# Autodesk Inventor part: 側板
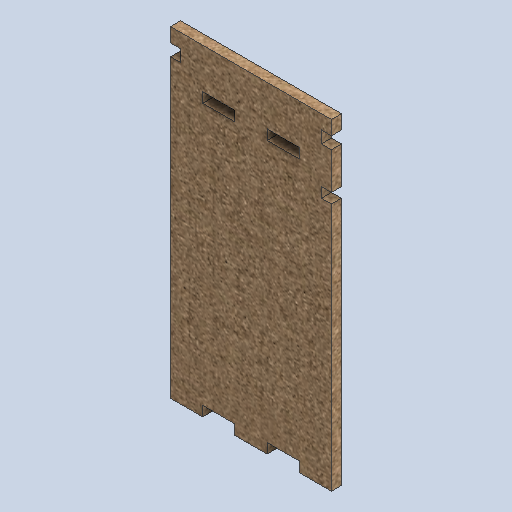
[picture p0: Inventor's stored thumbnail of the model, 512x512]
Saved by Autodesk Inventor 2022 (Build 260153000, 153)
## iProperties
Created: 2024-11
Part Number: 側板
Material: MDF 中密度繊維ボード
Document SubType Name: Modeling
Designer: shimizu
Density: 0.8 g/cm^3
Appearance: ダンボール - 段ボール紙
Author: shimizu
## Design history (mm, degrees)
sketch "スケッチ1"
  geometry: L1 (-20.243, 58.107)-(19.757, 58.107); L2 (-4.243, -21.893)-(-4.243, -19.393); L3 (-4.243, -19.393)-(-12.243, -19.393); L4 (-12.243, -19.393)-(-12.243, -21.893); L5 (11.757, -21.893)-(11.757, -19.393); L6 (11.757, -19.393)-(3.757, -19.393); L7 (3.757, -19.393)-(3.757, -21.893); L8 (-12.243, 48.107)-(-4.243, 48.107); L9 (-4.243, 48.107)-(-4.243, 45.607); L10 (-4.243, 45.607)-(-12.243, 45.607); L11 (-12.243, 45.607)-(-12.243, 48.107); L12 (3.757, 48.107)-(11.757, 48.107); L13 (11.757, 48.107)-(11.757, 45.607); L14 (11.757, 45.607)-(3.757, 45.607); L15 (3.757, 45.607)-(3.757, 48.107); L16 (-12.243, -21.893)-(-20.243, -21.893); L17 (19.757, -21.893)-(11.757, -21.893); L18 (3.757, -21.893)-(-4.243, -21.893); L19 (-20.243, 54.607)-(-17.743, 54.607); L20 (-17.743, 54.607)-(-17.743, 51.607); L21 (-17.743, 51.607)-(-20.243, 51.607); L22 (19.757, 54.607)-(17.257, 54.607); L23 (17.257, 54.607)-(17.257, 51.607); L24 (17.257, 51.607)-(19.757, 51.607); L25 (-20.243, -21.893)-(-20.243, 51.607); L26 (-20.243, 54.607)-(-20.243, 58.107); L27 (19.757, 58.107)-(19.757, 54.607); L28 (19.757, 51.607)-(19.757, -21.893); L29 (19.757, 42.427)-(17.257, 42.427); L30 (17.257, 42.427)-(17.257, 39.917); L31 (17.257, 39.917)-(19.757, 39.917); L32 (19.757, 39.917)-(19.757, 42.427); L33 (-20.243, -13.712)-(-17.743, -13.712); L34 (-17.743, -13.712)-(-17.743, -16.212); L35 (-17.743, -16.212)-(-20.243, -16.212); L36 (-20.243, -16.212)-(-20.243, -13.712); 3 further points
  constraints: 72 end point, 19 parallel, 8 perpendicular, 7 horizontal, 2 point on line
  dimensions: "d27" = 80 distance between parallel lines of L17 L1; "d28" = 40 distance between parallel lines of L25 L28; "d29" = 3.18 distance between parallel lines of L29 L14; "d30" = 2.5 distance of L30.end L31.end; "d31" = 2.5 distance between parallel lines of L16 L3; "d32" = 3.181 distance between parallel lines of L3 L35; "d33" = 2.5 distance of L33.end L34.end; "d34" = 2.5 distance between parallel lines of L36 L34; "d35" = 2.51 distance between parallel lines of L29 L31
extrude "押し出し1" new body sketch "スケッチ1" distance "d13" = 2.5; taper "d14" = 0 deg
node "ソリッド1"
